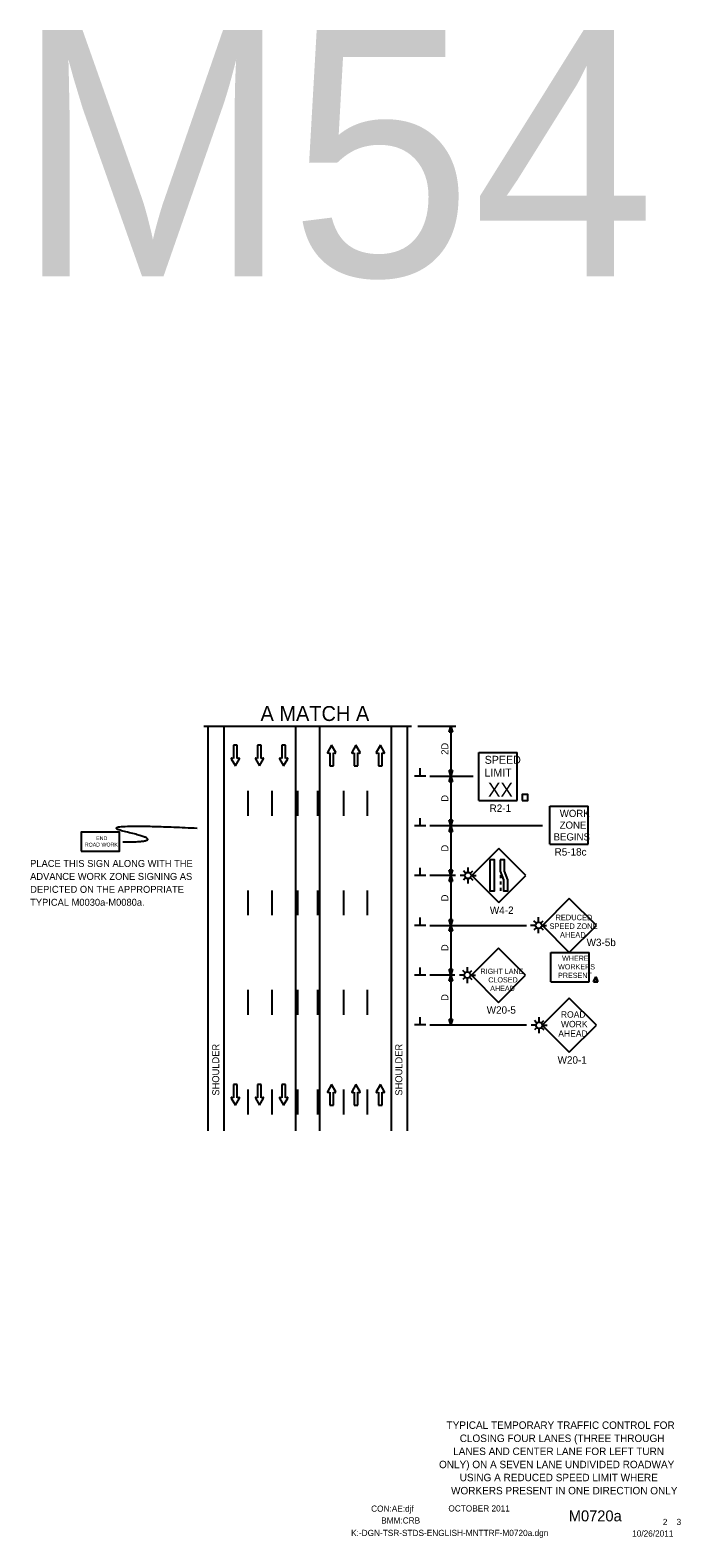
# Model space of a CAD drawing. Extents: x 16726 to 19504, y 5932 to 7446.
# Drawn here: x 17777 to 18431, y 5932 to 7446 of the extents above; entities that cross this region are included whole.
import ezdxf

# ---------------------------------------------------------------- set-up
doc = ezdxf.new("R2010")
doc.units = 0
for name, color, linetype in [('ALI_LEGAL_EX', 7, 'Continuous'), ('BORDER', 7, 'Continuous'), ('BORDER_SIGNAL_WO', 7, 'Continuous'), ('MT_SCRATCH_LEVEL_E', 7, 'Continuous'), ('PAVT_EDGE_EX', 7, 'Continuous'), ('TRAFFIC_SIGNS_PR', 7, 'Continuous'), ('TYPICAL_TEXT_DIMEN_PR', 7, 'Continuous')]:
    doc.layers.add(name, color=color, linetype=linetype)

msp = doc.modelspace()

# ---------------------------------------------------------------- linework, layer by layer
at = {"layer": 'ALI_LEGAL_EX'}
for points in [[(17995.8, 6682.2), (17995.8, 6657.2)], [(18019.8, 6682.2), (18019.8, 6657.2)], [(18045.8, 6682.2), (18045.8, 6657.2)], [(18065.8, 6682.2), (18065.8, 6657.2)], [(18091.8, 6682.2), (18091.8, 6657.2)], [(18115.8, 6682.2), (18115.8, 6657.2)], [(17995.8, 6582.2), (17995.8, 6557.2)], [(18019.8, 6582.2), (18019.8, 6557.2)], [(18045.8, 6582.2), (18045.8, 6557.2)], [(18065.8, 6582.2), (18065.8, 6557.2)], [(18091.8, 6582.2), (18091.8, 6557.2)], [(18115.8, 6582.2), (18115.8, 6557.2)], [(17995.8, 6482.2), (17995.8, 6457.2)], [(18019.8, 6482.2), (18019.8, 6457.2)], [(18045.8, 6482.2), (18045.8, 6457.2)], [(18065.8, 6482.2), (18065.8, 6457.2)], [(18091.8, 6482.2), (18091.8, 6457.2)], [(18115.8, 6482.2), (18115.8, 6457.2)], [(17995.8, 6382.2), (17995.8, 6357.2)], [(18019.8, 6382.2), (18019.8, 6357.2)], [(18045.8, 6382.2), (18045.8, 6357.2)], [(18065.8, 6382.2), (18065.8, 6357.2)], [(18091.8, 6382.2), (18091.8, 6357.2)], [(18115.8, 6382.2), (18115.8, 6357.2)]]:
    msp.add_lwpolyline(points, dxfattribs=at)
at = {"layer": 'BORDER'}
msp.add_line((18318.2, 6011.2), (18318.2, 6011.2), dxfattribs=at)
msp.add_line((18318.2, 6011.2), (18318.2, 6011.2), dxfattribs=at)
at = {"layer": 'MT_SCRATCH_LEVEL_E'}
for p, q in [((17985.2, 6727.9), (17981.4, 6727.9)), ((17981.4, 6727.9), (17981.4, 6714.7)), ((17985.2, 6727.9), (17981.4, 6727.9)), ((17981.4, 6727.9), (17981.4, 6714.7)), ((17985.2, 6714.7), (17985.2, 6727.9)), ((17985.2, 6714.7), (17985.2, 6727.9)), ((18009.4, 6727.9), (18005.7, 6727.9)), ((18005.7, 6727.9), (18005.7, 6714.7)), ((18009.4, 6727.9), (18005.7, 6727.9)), ((18005.7, 6727.9), (18005.7, 6714.7)), ((18009.4, 6714.7), (18009.4, 6727.9)), ((18009.4, 6714.7), (18009.4, 6727.9)), ((18033.7, 6727.9), (18030, 6727.9)), ((18030, 6727.9), (18030, 6714.7)), ((18033.7, 6727.9), (18030, 6727.9)), ((18030, 6727.9), (18030, 6714.7)), ((18033.7, 6714.7), (18033.7, 6727.9)), ((18033.7, 6714.7), (18033.7, 6727.9)), ((18080, 6727.9), (18075.9, 6720.7)), ((18080, 6727.9), (18075.9, 6720.7)), ((18084.2, 6720.7), (18080, 6727.9)), ((18084.2, 6720.7), (18080, 6727.9)), ((18104.5, 6727.9), (18100.4, 6720.7)), ((18104.5, 6727.9), (18100.4, 6720.7)), ((18108.7, 6720.7), (18104.5, 6727.9)), ((18108.7, 6720.7), (18104.5, 6727.9)), ((18129, 6727.9), (18124.9, 6720.7)), ((18129, 6727.9), (18124.9, 6720.7)), ((18133.2, 6720.7), (18129, 6727.9)), ((18133.2, 6720.7), (18129, 6727.9)), ((17979.2, 6714.3), (17983.3, 6707.1)), ((17979.2, 6714.3), (17983.3, 6707.1)), ((17981.4, 6714.7), (17979.7, 6715)), ((17981.4, 6714.7), (17979.7, 6715)), ((17983.3, 6707.1), (17987.4, 6714.3)), ((17983.3, 6707.1), (17987.4, 6714.3)), ((17987, 6715), (17985.2, 6714.7)), ((17987, 6715), (17985.2, 6714.7)), ((18003.4, 6714.3), (18007.6, 6707.1)), ((18003.4, 6714.3), (18007.6, 6707.1)), ((18005.7, 6714.7), (18003.9, 6715)), ((18005.7, 6714.7), (18003.9, 6715)), ((18007.6, 6707.1), (18011.7, 6714.3)), ((18007.6, 6707.1), (18011.7, 6714.3)), ((18011.2, 6715), (18009.4, 6714.7)), ((18011.2, 6715), (18009.4, 6714.7)), ((18027.7, 6714.3), (18031.8, 6707.1)), ((18027.7, 6714.3), (18031.8, 6707.1)), ((18030, 6714.7), (18028.2, 6715)), ((18030, 6714.7), (18028.2, 6715)), ((18031.8, 6707.1), (18036, 6714.3)), ((18031.8, 6707.1), (18036, 6714.3)), ((18035.5, 6715), (18033.7, 6714.7)), ((18035.5, 6715), (18033.7, 6714.7)), ((18076.4, 6720), (18078.2, 6720.3)), ((18076.4, 6720), (18078.2, 6720.3)), ((18078.2, 6720.3), (18078.2, 6707.1)), ((18078.2, 6720.3), (18078.2, 6707.1)), ((18081.9, 6707.1), (18081.9, 6720.3)), ((18081.9, 6720.3), (18083.7, 6720)), ((18081.9, 6707.1), (18081.9, 6720.3)), ((18081.9, 6720.3), (18083.7, 6720)), ((18100.9, 6720), (18102.7, 6720.3)), ((18100.9, 6720), (18102.7, 6720.3)), ((18102.7, 6720.3), (18102.7, 6707.1)), ((18102.7, 6720.3), (18102.7, 6707.1)), ((18106.4, 6707.1), (18106.4, 6720.3)), ((18106.4, 6720.3), (18108.2, 6720)), ((18106.4, 6707.1), (18106.4, 6720.3)), ((18106.4, 6720.3), (18108.2, 6720)), ((18125.4, 6720), (18127.2, 6720.3)), ((18125.4, 6720), (18127.2, 6720.3)), ((18127.2, 6720.3), (18127.2, 6707.1)), ((18127.2, 6720.3), (18127.2, 6707.1)), ((18130.9, 6707.1), (18130.9, 6720.3)), ((18130.9, 6720.3), (18132.7, 6720)), ((18130.9, 6707.1), (18130.9, 6720.3)), ((18130.9, 6720.3), (18132.7, 6720)), ((18078.2, 6707.1), (18081.9, 6707.1)), ((18078.2, 6707.1), (18081.9, 6707.1)), ((18102.7, 6707.1), (18106.4, 6707.1)), ((18102.7, 6707.1), (18106.4, 6707.1)), ((18127.2, 6707.1), (18130.9, 6707.1)), ((18127.2, 6707.1), (18130.9, 6707.1)), ((17985.2, 6387.1), (17981.4, 6387.1)), ((17981.4, 6387.1), (17981.4, 6373.9)), ((17985.2, 6387.1), (17981.4, 6387.1)), ((17981.4, 6387.1), (17981.4, 6373.9)), ((17985.2, 6373.9), (17985.2, 6387.1)), ((17985.2, 6373.9), (17985.2, 6387.1)), ((18009.4, 6387.1), (18005.7, 6387.1)), ((18005.7, 6387.1), (18005.7, 6373.9)), ((18009.4, 6387.1), (18005.7, 6387.1)), ((18005.7, 6387.1), (18005.7, 6373.9)), ((18009.4, 6373.9), (18009.4, 6387.1)), ((18009.4, 6373.9), (18009.4, 6387.1)), ((18033.7, 6387.1), (18030, 6387.1)), ((18030, 6387.1), (18030, 6373.9)), ((18033.7, 6387.1), (18030, 6387.1)), ((18030, 6387.1), (18030, 6373.9)), ((18033.7, 6373.9), (18033.7, 6387.1)), ((18033.7, 6373.9), (18033.7, 6387.1)), ((18080, 6387.1), (18075.9, 6379.9)), ((18080, 6387.1), (18075.9, 6379.9)), ((18076.4, 6379.2), (18078.2, 6379.5)), ((18076.4, 6379.2), (18078.2, 6379.5)), ((18078.2, 6379.5), (18078.2, 6366.3)), ((18078.2, 6379.5), (18078.2, 6366.3)), ((18084.2, 6379.9), (18080, 6387.1)), ((18084.2, 6379.9), (18080, 6387.1)), ((18081.9, 6366.3), (18081.9, 6379.5)), ((18081.9, 6379.5), (18083.7, 6379.2)), ((18081.9, 6366.3), (18081.9, 6379.5)), ((18081.9, 6379.5), (18083.7, 6379.2)), ((18104.5, 6387.1), (18100.4, 6379.9)), ((18104.5, 6387.1), (18100.4, 6379.9)), ((18100.9, 6379.2), (18102.7, 6379.5)), ((18100.9, 6379.2), (18102.7, 6379.5)), ((18102.7, 6379.5), (18102.7, 6366.3)), ((18102.7, 6379.5), (18102.7, 6366.3)), ((18108.7, 6379.9), (18104.5, 6387.1)), ((18108.7, 6379.9), (18104.5, 6387.1)), ((18106.4, 6366.3), (18106.4, 6379.5)), ((18106.4, 6379.5), (18108.2, 6379.2)), ((18106.4, 6366.3), (18106.4, 6379.5)), ((18106.4, 6379.5), (18108.2, 6379.2)), ((18129, 6387.1), (18124.9, 6379.9)), ((18129, 6387.1), (18124.9, 6379.9)), ((18125.4, 6379.2), (18127.2, 6379.5)), ((18125.4, 6379.2), (18127.2, 6379.5)), ((18127.2, 6379.5), (18127.2, 6366.3)), ((18127.2, 6379.5), (18127.2, 6366.3)), ((18133.2, 6379.9), (18129, 6387.1)), ((18133.2, 6379.9), (18129, 6387.1)), ((18130.9, 6366.3), (18130.9, 6379.5)), ((18130.9, 6379.5), (18132.7, 6379.2)), ((18130.9, 6366.3), (18130.9, 6379.5)), ((18130.9, 6379.5), (18132.7, 6379.2)), ((17979.2, 6373.5), (17983.3, 6366.3)), ((17979.2, 6373.5), (17983.3, 6366.3)), ((17981.4, 6373.9), (17979.7, 6374.2)), ((17981.4, 6373.9), (17979.7, 6374.2)), ((17983.3, 6366.3), (17987.4, 6373.5)), ((17983.3, 6366.3), (17987.4, 6373.5)), ((17987, 6374.2), (17985.2, 6373.9)), ((17987, 6374.2), (17985.2, 6373.9)), ((18003.4, 6373.5), (18007.6, 6366.3)), ((18003.4, 6373.5), (18007.6, 6366.3)), ((18005.7, 6373.9), (18003.9, 6374.2)), ((18005.7, 6373.9), (18003.9, 6374.2)), ((18007.6, 6366.3), (18011.7, 6373.5)), ((18007.6, 6366.3), (18011.7, 6373.5)), ((18011.2, 6374.2), (18009.4, 6373.9)), ((18011.2, 6374.2), (18009.4, 6373.9)), ((18027.7, 6373.5), (18031.8, 6366.3)), ((18027.7, 6373.5), (18031.8, 6366.3)), ((18030, 6373.9), (18028.2, 6374.2)), ((18030, 6373.9), (18028.2, 6374.2)), ((18031.8, 6366.3), (18036, 6373.5)), ((18031.8, 6366.3), (18036, 6373.5)), ((18035.5, 6374.2), (18033.7, 6373.9)), ((18035.5, 6374.2), (18033.7, 6373.9)), ((18078.2, 6366.3), (18081.9, 6366.3)), ((18078.2, 6366.3), (18081.9, 6366.3)), ((18102.7, 6366.3), (18106.4, 6366.3)), ((18102.7, 6366.3), (18106.4, 6366.3)), ((18127.2, 6366.3), (18130.9, 6366.3)), ((18127.2, 6366.3), (18130.9, 6366.3))]:
    msp.add_line(p, q, dxfattribs=at)
for centre, start, end in [((17979.6, 6714.5), 80.0362, 209.7731), ((17979.6, 6714.5), 80.0362, 209.7731), ((17987, 6714.5), 330.4248, 99.9638), ((17987, 6714.5), 330.4248, 99.9638), ((18003.8, 6714.5), 80.0362, 209.7731), ((18003.8, 6714.5), 80.0362, 209.7731), ((18011.3, 6714.5), 330.4248, 99.9638), ((18011.3, 6714.5), 330.4248, 99.9638), ((18028.1, 6714.5), 80.0362, 209.7731), ((18028.1, 6714.5), 80.0362, 209.7731), ((18035.5, 6714.5), 330.4248, 99.9638), ((18035.5, 6714.5), 330.4248, 99.9638), ((18076.3, 6720.5), 150.4248, 279.9638), ((18076.3, 6720.5), 150.4248, 279.9638), ((18083.7, 6720.5), 260.0362, 29.7731), ((18083.7, 6720.5), 260.0362, 29.7731), ((18100.8, 6720.5), 150.4248, 279.9638), ((18100.8, 6720.5), 150.4248, 279.9638), ((18108.2, 6720.5), 260.0362, 29.7731), ((18108.2, 6720.5), 260.0362, 29.7731), ((18125.3, 6720.5), 150.4248, 279.9638), ((18125.3, 6720.5), 150.4248, 279.9638), ((18132.7, 6720.5), 260.0362, 29.7731), ((18132.7, 6720.5), 260.0362, 29.7731), ((18076.3, 6379.7), 150.4248, 279.9638), ((18076.3, 6379.7), 150.4248, 279.9638), ((18083.7, 6379.7), 260.0362, 29.7731), ((18083.7, 6379.7), 260.0362, 29.7731), ((18100.8, 6379.7), 150.4248, 279.9638), ((18100.8, 6379.7), 150.4248, 279.9638), ((18108.2, 6379.7), 260.0362, 29.7731), ((18108.2, 6379.7), 260.0362, 29.7731), ((18125.3, 6379.7), 150.4248, 279.9638), ((18125.3, 6379.7), 150.4248, 279.9638), ((18132.7, 6379.7), 260.0362, 29.7731), ((18132.7, 6379.7), 260.0362, 29.7731), ((17979.6, 6373.7), 80.0362, 209.7731), ((17979.6, 6373.7), 80.0362, 209.7731), ((17987, 6373.7), 330.4248, 99.9638), ((17987, 6373.7), 330.4248, 99.9638), ((18003.8, 6373.7), 80.0362, 209.7731), ((18003.8, 6373.7), 80.0362, 209.7731), ((18011.3, 6373.7), 330.4248, 99.9638), ((18011.3, 6373.7), 330.4248, 99.9638), ((18028.1, 6373.7), 80.0362, 209.7731), ((18028.1, 6373.7), 80.0362, 209.7731), ((18035.5, 6373.7), 330.4248, 99.9638), ((18035.5, 6373.7), 330.4248, 99.9638)]:
    msp.add_arc(centre, 0.463, start, end, dxfattribs=at)
at = {"layer": 'PAVT_EDGE_EX'}
for p, q in [((17955.8, 6747), (17955.8, 6340.8)), ((17971.8, 6747), (17971.8, 6340.8)), ((18043.8, 6747), (18043.8, 6340.8)), ((18067.8, 6747), (18067.8, 6340.8)), ((18139.8, 6747), (18139.8, 6340.8)), ((18155.8, 6747), (18155.8, 6340.8))]:
    msp.add_line(p, q, dxfattribs=at)
at = {"layer": 'TRAFFIC_SIGNS_PR'}
for p, q in [((18228, 6720.5), (18266.4, 6720.5)), ((18228, 6672.5), (18228, 6720.5)), ((18266.4, 6672.5), (18266.4, 6720.5)), ((18228, 6672.5), (18266.4, 6672.5)), ((18299.2, 6628.5), (18299.2, 6666.9)), ((18299.2, 6666.9), (18337.6, 6666.9)), ((18337.6, 6628.5), (18337.6, 6666.9)), ((18248, 6624.2), (18220.9, 6597.1)), ((18275.2, 6597.1), (18248, 6624.2)), ((18299.2, 6628.5), (18337.6, 6628.5)), ((18217.1, 6600.6), (18217.1, 6605.1)), ((18214, 6597.1), (18209.1, 6597.1)), ((18214.6, 6599.6), (18212.5, 6601.7)), ((18214.6, 6594.6), (18212.5, 6592.4)), ((18217.1, 6589.1), (18217.1, 6593.5)), ((18219.6, 6599.6), (18221.8, 6601.7)), ((18219.6, 6594.6), (18221.8, 6592.4)), ((18220.3, 6597.1), (18225.2, 6597.1)), ((18220.9, 6597.1), (18248, 6569.9)), ((18248, 6569.9), (18275.2, 6597.1)), ((18249.7, 6597.6), (18249.7, 6594.4)), ((18249.7, 6591.2), (18249.7, 6588)), ((18249.7, 6584.8), (18249.7, 6581.6)), ((18318.8, 6574.1), (18291.7, 6546.9)), ((18346, 6546.9), (18318.8, 6574.1)), ((18284.7, 6547), (18279.9, 6547)), ((18285.4, 6549.6), (18283.3, 6551.7)), ((18285.4, 6544.5), (18283.3, 6542.4)), ((18287.9, 6550.6), (18287.9, 6555.1)), ((18287.9, 6539.1), (18287.9, 6543.5)), ((18290.4, 6549.6), (18292.5, 6551.7)), ((18290.4, 6544.5), (18292.5, 6542.4)), ((18291, 6547), (18295.9, 6547)), ((18291.7, 6546.9), (18318.8, 6519.8)), ((18318.8, 6519.8), (18346, 6546.9)), ((18247.6, 6524), (18220.5, 6496.9)), ((18274.8, 6496.9), (18247.6, 6524)), ((18300.2, 6519.7), (18338.6, 6519.7)), ((18300.2, 6490.4), (18300.2, 6519.7)), ((18338.6, 6490.4), (18338.6, 6519.7)), ((18213.2, 6497.1), (18208.4, 6497.1)), ((18213.9, 6499.6), (18211.8, 6501.7)), ((18216.4, 6500.6), (18216.4, 6505.1)), ((18218.9, 6499.6), (18221, 6501.7)), ((18219.5, 6497.1), (18224.4, 6497.1)), ((18220.5, 6496.9), (18247.6, 6469.7)), ((18247.6, 6469.7), (18274.8, 6496.9)), ((18213.9, 6494.6), (18211.8, 6492.5)), ((18216.4, 6489.1), (18216.4, 6493.5)), ((18218.9, 6494.6), (18221, 6492.5)), ((18300.2, 6490.4), (18338.6, 6490.4)), ((18318.8, 6473.9), (18291.6, 6446.7)), ((18346, 6446.7), (18318.8, 6473.9)), ((18285.9, 6449.2), (18283.8, 6451.4)), ((18288.5, 6450.3), (18288.5, 6454.8)), ((18291, 6449.2), (18293.1, 6451.4)), ((18285.3, 6446.7), (18280.5, 6446.7)), ((18285.9, 6444.2), (18283.8, 6442.1)), ((18288.5, 6438.8), (18288.5, 6443.2)), ((18291, 6444.2), (18293.1, 6442.1)), ((18291.6, 6446.7), (18296.5, 6446.7)), ((18291.6, 6446.7), (18318.8, 6419.5)), ((18318.8, 6419.5), (18346, 6446.7))]:
    msp.add_line(p, q, dxfattribs=at)
for points in [[(18271.4, 6672.5), (18277, 6672.5), (18277, 6678.6), (18271.4, 6678.6)], [(17828.5, 6621.4), (17866.9, 6621.4), (17866.9, 6640.6), (17828.5, 6640.6)], [(18239.1, 6612.8), (18239.1, 6581.6), (18243.6, 6581.6), (18243.6, 6612.8)], [(18249.3, 6612.8), (18249.3, 6601.6), (18252.6, 6592.7), (18252.6, 6581.6), (18257.1, 6581.6), (18257.1, 6592.7), (18253.8, 6601.6), (18253.8, 6612.8)]]:
    msp.add_lwpolyline(points, close=True, dxfattribs=at)
for points in [[(18345.3, 6495.3), (18343.1, 6490.4)], [(18343.1, 6490.4), (18345.3, 6495.3)], [(18343.1, 6490.4), (18347.5, 6490.4)], [(18347.5, 6490.4), (18343.1, 6490.4)], [(18347.5, 6490.4), (18345.3, 6495.3)], [(18345.3, 6495.3), (18347.5, 6490.4)]]:
    msp.add_lwpolyline(points, dxfattribs=at)
for centre in [(18217.1, 6597.1), (18287.9, 6547), (18216.4, 6497.1), (18288.5, 6446.7)]:
    msp.add_circle(centre, 3.15, dxfattribs=at)
msp.add_open_spline([(17870.4, 6630.8), (17917.7, 6630.8), (17832.7, 6650.2), (17945, 6644.7)], degree=2, dxfattribs=at)
at = {"layer": 'TYPICAL_TEXT_DIMEN_PR'}
for p, q in [((17951.5, 6747), (18160.1, 6747)), ((18043.8, 6747), (18067.8, 6747)), ((18166.5, 6747), (18204.8, 6747)), ((18198.2, 6741.1), (18199.8, 6747)), ((18199.8, 6741.1), (18198.2, 6741.1)), ((18199.8, 6747), (18201.3, 6741.1)), ((18199.8, 6747), (18199.8, 6697)), ((18201.3, 6741.1), (18199.8, 6741.1)), ((18174.5, 6697), (18163.3, 6697)), ((18168.9, 6697), (18168.9, 6704.8)), ((18178.8, 6697), (18222.3, 6697)), ((18199.8, 6697), (18198.2, 6702.9)), ((18198.2, 6702.9), (18199.8, 6702.9)), ((18198.2, 6691.1), (18199.8, 6697)), ((18199.8, 6702.9), (18201.3, 6702.9)), ((18201.3, 6702.9), (18199.8, 6697)), ((18199.8, 6697), (18201.3, 6691.1)), ((18199.8, 6697), (18199.8, 6647)), ((18199.8, 6691.1), (18198.2, 6691.1)), ((18201.3, 6691.1), (18199.8, 6691.1)), ((18168.9, 6647), (18168.9, 6654.8)), ((18199.8, 6647), (18198.2, 6652.9)), ((18198.2, 6652.9), (18199.8, 6652.9)), ((18199.8, 6652.9), (18201.3, 6652.9)), ((18201.3, 6652.9), (18199.8, 6647)), ((18174.5, 6647), (18163.3, 6647)), ((18292, 6647), (18178.8, 6647)), ((18198.2, 6641.1), (18199.8, 6647)), ((18199.8, 6641.1), (18198.2, 6641.1)), ((18199.8, 6647), (18201.3, 6641.1)), ((18199.8, 6647), (18199.8, 6597)), ((18201.3, 6641.1), (18199.8, 6641.1)), ((18168.9, 6597), (18168.9, 6604.8)), ((18199.8, 6597), (18198.2, 6602.9)), ((18198.2, 6602.9), (18199.8, 6602.9)), ((18199.8, 6602.9), (18201.3, 6602.9)), ((18201.3, 6602.9), (18199.8, 6597)), ((18174.5, 6597), (18163.3, 6597)), ((18204.5, 6597), (18178.8, 6597)), ((18198.2, 6591.1), (18199.8, 6597)), ((18199.8, 6591.1), (18198.2, 6591.1)), ((18199.8, 6597), (18201.3, 6591.1)), ((18199.8, 6597), (18199.8, 6547)), ((18201.3, 6591.1), (18199.8, 6591.1)), ((18174.5, 6547), (18163.3, 6547)), ((18168.9, 6547), (18168.9, 6554.8)), ((18178.8, 6547), (18275.8, 6547)), ((18199.8, 6547), (18198.2, 6552.9)), ((18198.2, 6552.9), (18199.8, 6552.9)), ((18198.2, 6541.1), (18199.8, 6547)), ((18199.8, 6552.9), (18201.3, 6552.9)), ((18201.3, 6552.9), (18199.8, 6547)), ((18199.8, 6547), (18201.3, 6541.1)), ((18199.8, 6547), (18199.8, 6497)), ((18199.8, 6541.1), (18198.2, 6541.1)), ((18201.3, 6541.1), (18199.8, 6541.1)), ((18174.5, 6497), (18163.3, 6497)), ((18168.9, 6497), (18168.9, 6504.8)), ((18203.7, 6497), (18178.8, 6497)), ((18199.8, 6497), (18198.2, 6502.9)), ((18198.2, 6502.9), (18199.8, 6502.9)), ((18198.2, 6491.1), (18199.8, 6497)), ((18199.8, 6502.9), (18201.3, 6502.9)), ((18201.3, 6502.9), (18199.8, 6497)), ((18199.8, 6497), (18201.3, 6491.1)), ((18199.8, 6497), (18199.8, 6447)), ((18199.8, 6491.1), (18198.2, 6491.1)), ((18201.3, 6491.1), (18199.8, 6491.1)), ((18168.9, 6447), (18168.9, 6454.8)), ((18199.8, 6447), (18198.2, 6452.9)), ((18198.2, 6452.9), (18199.8, 6452.9)), ((18199.8, 6452.9), (18201.3, 6452.9)), ((18201.3, 6452.9), (18199.8, 6447)), ((18174.5, 6447), (18163.3, 6447)), ((18178.8, 6447), (18275.8, 6447))]:
    msp.add_line(p, q, dxfattribs=at)

# ---------------------------------------------------------------- texts
at = {"layer": 'BORDER_SIGNAL_WO'}
for s, height, p in [('TYPICAL TEMPORARY TRAFFIC CONTROL FOR ', 7.502, (18195.5, 6041.3)), ('CLOSING FOUR LANES (THREE THROUGH ', 7.502, (18208.7, 6028.1)), ('LANES AND CENTER LANE FOR LEFT TURN ', 7.502, (18202.1, 6015)), ('ONLY) ON A SEVEN LANE UNDIVIDED ROADWAY ', 7.502, (18187.9, 6001.8)), ('WORKERS PRESENT IN ONE DIRECTION ONLY', 7.502, (18200, 5975.5)), ('USING A REDUCED SPEED LIMIT WHERE ', 7.502, (18208.7, 5988.7)), ('CON:AE:djf', 6.2, (18119.7, 5958.1)), ('BMM:CRB   ', 6.2, (18129.8, 5946.2)), ('    OCTOBER 2011    ', 6.2, (18188.1, 5958.3)), ('    M0720a   ', 11, (18301.9, 5948.4)), ('K:-DGN-TSR-STDS-ENGLISH-MNTTRF-M0720a.dgn        ', 6.2, (18099.6, 5933.7)), ('10/26/2011    ', 6.2, (18381.9, 5933.1)), (' 2    3 ', 6.2, (18410.4, 5944.7))]:
    msp.add_text(s, height=height, dxfattribs=at).set_placement(p)
at = {"layer": 'TRAFFIC_SIGNS_PR'}
for s, height, p in [('SPEED', 8, (18233.8, 6709.3)), ('LIMIT', 8, (18233.6, 6696.5)), ('XX', 14.03, (18237.1, 6676.2)), ('R2-1', 7.44, (18238.7, 6661)), ('WORK', 7.22, (18309.2, 6655.9)), ('ZONE', 7.22, (18309.1, 6644.1)), ('END', 3.83, (17843.5, 6632.6)), ('BEGINS', 7.22, (18303, 6632.3)), ('ROAD WORK', 3.83, (17832.1, 6626.2)), ('R5-18c', 7.44, (18304, 6617.1)), ('PLACE THIS SIGN ALONG WITH THE', 7, (17777.2, 6605.7)), ('ADVANCE WORK ZONE SIGNING AS', 7, (17777.2, 6592.7)), ('TYPICAL M0030a-M0080a.', 7, (17777.2, 6566.7)), ('DEPICTED ON THE APPROPRIATE', 7, (17777.2, 6579.7)), ('W4-2', 7.44, (18239, 6558.5)), ('REDUCED', 5.6, (18304.9, 6552.2)), ('SPEED ZONE', 5.6, (18298.9, 6543.4)), ('AHEAD', 5.6, (18309.4, 6534.6)), ('W3-5b', 7.44, (18336.2, 6526.2)), ('WHERE', 5.2, (18311.5, 6511.4)), ('RIGHT LANE', 5.2, (18229.6, 6498.3)), ('WORKERS', 5.2, (18307.5, 6502.8)), ('PRESENT', 5.2, (18307.5, 6494.2)), ('CLOSED', 5.2, (18237.4, 6489.7)), ('AHEAD', 5.2, (18239.3, 6481.1)), ('W20-5', 7.44, (18235.8, 6458.3)), ('WORK', 6.41, (18310.4, 6444.7)), ('ROAD', 6.41, (18310.3, 6454.3)), ('AHEAD', 6.41, (18307.7, 6435.1)), ('W20-1', 7.45, (18307, 6408.1))]:
    msp.add_text(s, height=height, dxfattribs=at).set_placement(p)
at = {"layer": 'TYPICAL_TEXT_DIMEN_PR'}
for s, height, p in [('M54', 247.21, (17762.2, 7199)), ('A MATCH A', 15, (18008.6, 6752.3))]:
    msp.add_text(s, height=height, dxfattribs=at).set_placement(p)
for s, p in [('2D', (18197.2, 6718.4)), ('D', (18197.2, 6671.2)), ('D', (18197.2, 6621.2)), ('D', (18197.2, 6571.2)), ('D', (18197.2, 6521.2)), ('D', (18197.2, 6471.2)), ('SHOULDER', (17967.1, 6376)), ('SHOULDER', (18151, 6376))]:
    msp.add_text(s, height=7, rotation=90, dxfattribs=at).set_placement(p)

doc.saveas('drawing.dxf')
